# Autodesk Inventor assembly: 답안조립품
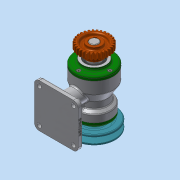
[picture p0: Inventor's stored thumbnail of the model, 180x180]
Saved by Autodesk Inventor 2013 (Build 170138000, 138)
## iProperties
Created: 2019-01
Part Number: 답안조립품
Document SubType Name: Assembly
Designer: Administrator
Author: Administrator
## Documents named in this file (15)
- C:\Users\Administrator\Desktop\490107V1010\답안조립품.iam
- C:\Users\Administrator\Desktop\490107V1010\본체.ipt
- C:\Users\Administrator\Desktop\490107V1010\베어링 6203.ipt
- C:\Users\Administrator\Desktop\490107V1010\베어링 6205.ipt
- C:\Users\Administrator\Desktop\490107V1010\앞커버.ipt
- C:\Users\Administrator\Desktop\490107V1010\뒤커버.ipt
- C:\Users\Administrator\Desktop\490107V1010\볼트 M4.ipt
- C:\Users\Administrator\Desktop\490107V1010\오일 실 25 38 8.ipt
- C:\Users\Administrator\Desktop\490107V1010\오일 실 17 30 8.ipt
- C:\Users\Administrator\Desktop\490107V1010\축.ipt
- C:\Users\Administrator\Desktop\490107V1010\키 6 x 6 x 18.ipt
- C:\Users\Administrator\Desktop\490107V1010\스퍼기어.ipt
- C:\Users\Administrator\Desktop\490107V1010\V-벨트풀리.ipt
- C:\Users\Administrator\Desktop\490107V1010\키 5 x 5 x 20.ipt
- C:\Users\Administrator\Desktop\490107V1010\멈춤나사 M3.ipt
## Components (1 placed, 1 different names)
1. V-벨트풀리:1 — 플러쉬:1
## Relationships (1: Flush 1)
- 플러쉬:1 [Flush]: V-벨트풀리:1
